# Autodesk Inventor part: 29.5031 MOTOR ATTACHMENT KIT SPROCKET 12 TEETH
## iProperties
Created: 2006-12
Part Number: 29.5031 MOTOR ATTACHMENT KIT SPROCKET 12 TEETH
Document SubType Name: Modeling
Designer: Andy Moles
Material: Steel
Density: 7.85 g/cm^3
Author: Andy Moles
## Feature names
1. Extrusion1
2. Extrusion2
3. Extrusion3
4. Circular Pattern1
5. Extrusion4
